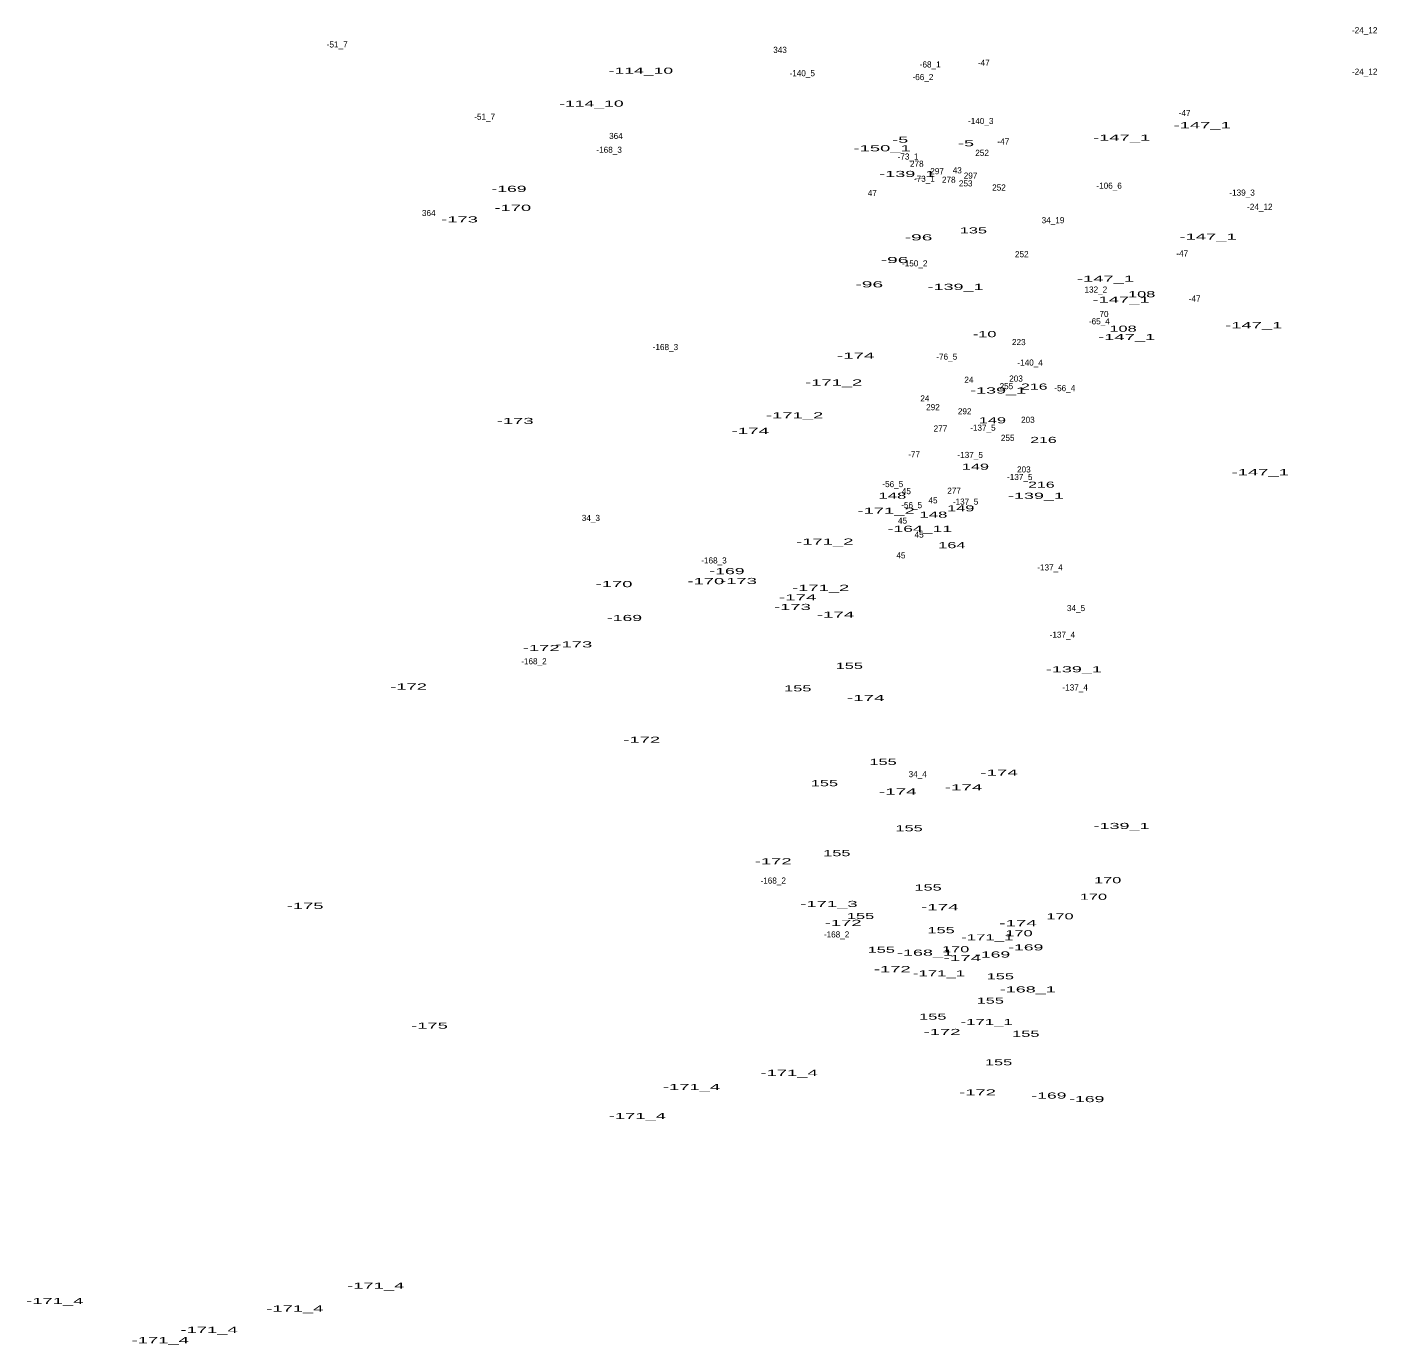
# Model space of a CAD drawing. Extents: x -662499 to -659675, y -1001682 to -998165.
# Drawn here: x -661898 to -661015, y -1001682 to -1000819 of the extents above; entities that cross this region are included whole.
import ezdxf
from ezdxf.enums import TextEntityAlignment as Align

# ---------------------------------------------------------------- set-up
doc = ezdxf.new("R2010")
doc.units = 0
doc.header["$LTSCALE"] = 1.6
doc.layers.add('24', color=7, linetype='Continuous')

msp = doc.modelspace()

# ---------------------------------------------------------------- texts
at = {"layer": '24'}
for s, p in [('-24_12', (-661022.76, -1000823.07)), ('-51_7', (-661695.372, -1000832.41)), ('343', (-661405.471, -1000835.95)), ('-140_5', (-661390.954, -1000851.22)), ('-68_1', (-661307.202, -1000845.5)), ('-47', (-661272.085, -1000844.32)), ('-24_12', (-661022.76, -1000850.22)), ('-66_2', (-661311.923, -1000853.76)), ('-47', (-661140.645, -1000877.29)), ('-51_7', (-661598.832, -1000879.73)), ('-140_3', (-661274.074, -1000882.52)), ('364', (-661512.907, -1000892.31)), ('-168_3', (-661517.342, -1000901.35)), ('252', (-661273.197, -1000903.34)), ('-47', (-661259.285, -1000895.91)), ('-73_1', (-661321.652, -1000905.77)), ('278', (-661315.953, -1000910.46)), ('-73_1', (-661310.992, -1000920.32)), ('297', (-661302.668, -1000915.34)), ('278', (-661295.013, -1000920.93)), ('43', (-661289.491, -1000914.82)), ('297', (-661280.758, -1000918.25)), ('47', (-661345.057, -1000929.67)), ('253', (-661283.937, -1000923.34)), ('252', (-661262.147, -1000926.03)), ('-106_6', (-661190.051, -1000924.83)), ('-139_3', (-661103.032, -1000929.38)), ('-24_12', (-661091.39, -1000938.66)), ('364', (-661635.427, -1000942.74)), ('34_19', (-661226.778, -1000947.42)), ('252', (-661247.217, -1000969.67)), ('-47', (-661142.195, -1000969.21)), ('-150_2', (-661317.3, -1000975.69)), ('132_2', (-661198.739, -1000992.85)), ('-47', (-661134.055, -1000998.69)), ('70', (-661193.407, -1001008.81)), ('-65_4', (-661196.452, -1001013.61)), ('223', (-661249.177, -1001027.2)), ('-168_3', (-661480.512, -1001030.45)), ('-76_5', (-661296.344, -1001036.71)), ('-140_4', (-661241.769, -1001040.61)), ('24', (-661281.841, -1001051.87)), ('203', (-661251.001, -1001051.07)), ('255', (-661257.317, -1001056.03)), ('-56_4', (-661219.052, -1001057.33)), ('24', (-661310.691, -1001064.08)), ('292', (-661305.373, -1001069.77)), ('292', (-661284.623, -1001072.48)), ('203', (-661243.241, -1001078.03)), ('277', (-661300.469, -1001083.78)), ('-137_5', (-661272.682, -1001083.22)), ('255', (-661256.447, -1001089.88)), ('-77', (-661317.735, -1001100.64)), ('-137_5', (-661281.022, -1001101.06)), ('-137_5', (-661248.552, -1001115.51)), ('203', (-661245.861, -1001110.52)), ('-56_5', (-661331.648, -1001120.13)), ('45', (-661322.771, -1001124.74)), ('277', (-661291.549, -1001124.49)), ('-56_5', (-661319.338, -1001133.9)), ('45', (-661305.351, -1001130.74)), ('-137_5', (-661284.032, -1001131.61)), ('34_3', (-661529.31, -1001142.28)), ('45', (-661325.291, -1001144.01)), ('45', (-661314.451, -1001153.21)), ('45', (-661326.361, -1001166.77)), ('-168_3', (-661448.712, -1001170.09)), ('-137_4', (-661228.776, -1001174.67)), ('34_5', (-661211.73, -1001201.26)), ('-137_4', (-661220.636, -1001218.7)), ('-168_2', (-661566.592, -1001236.08)), ('-137_4', (-661212.296, -1001253.22)), ('34_4', (-661315.374, -1001309.94)), ('-168_2', (-661409.942, -1001379.6)), ('-168_2', (-661368.462, -1001414.84))]:
    msp.add_text(s, height=4, dxfattribs=at).set_placement(p, align=Align.CENTER)
for s, width, p in [('-114_10', 2.15, (-661496.566, -1000849.59)), ('-114_10', 2.15, (-661528.946, -1000871.12)), ('-147_1', 2.25, (-661129.128, -1000885.24)), ('-5', 2.2, (-661326.774, -1000894.74)), ('-147_1', 2.25, (-661181.858, -1000893.38)), ('-150_1', 2.25, (-661338.634, -1000900.35)), ('-5', 2.2, (-661283.734, -1000897.07)), ('-139_1', 2.2, (-661322.193, -1000917.17)), ('-169', 2.15, (-661582.909, -1000926.91)), ('-170', 2.25, (-661580.431, -1000939.32)), ('-173', 2.25, (-661615.275, -1000946.92)), ('135', 2, (-661278.917, -1000954.11)), ('-96', 2.35, (-661314.813, -1000958.67)), ('-147_1', 2.25, (-661125.248, -1000958.16)), ('-96', 2.35, (-661330.523, -1000973.5)), ('-96', 2.35, (-661347.093, -1000989.41)), ('-139_1', 2.2, (-661290.593, -1000991.06)), ('-147_1', 2.25, (-661192.428, -1000985.74)), ('-147_1', 2.25, (-661182.248, -1000999.41)), ('108', 2, (-661168.744, -1000995.86)), ('108', 2, (-661180.934, -1001018.43)), ('-147_1', 2.25, (-661095.398, -1001016.14)), ('-10', 2, (-661271.557, -1001022)), ('-147_1', 2.25, (-661178.568, -1001023.94)), ('-174', 2.3, (-661355.941, -1001036.05)), ('-171_2', 2.25, (-661370.363, -1001053.62)), ('-139_1', 2.2, (-661262.753, -1001058.86)), ('216', 1.95, (-661239.063, -1001056.33)), ('-173', 2.25, (-661578.835, -1001078.8)), ('-171_2', 2.25, (-661395.953, -1001075.14)), ('149', 2, (-661266.458, -1001078.39)), ('-174', 2.3, (-661424.961, -1001085.31)), ('216', 1.95, (-661233.053, -1001091.24)), ('149', 2, (-661277.598, -1001108.74)), ('-147_1', 2.25, (-661091.128, -1001112.33)), ('216', 1.95, (-661234.413, -1001120.52)), ('148', 2.05, (-661331.933, -1001127.72)), ('-139_1', 2.2, (-661237.943, -1001127.78)), ('-171_2', 2.25, (-661336.043, -1001137.59)), ('148', 2.05, (-661305.083, -1001140.14)), ('149', 2, (-661287.198, -1001135.99)), ('-164_11', 2.15, (-661313.975, -1001149.39)), ('-171_2', 2.25, (-661376.173, -1001157.76)), ('164', 2, (-661293.008, -1001160.1)), ('-169', 2.15, (-661440.219, -1001177.09)), ('-170', 2.25, (-661514.131, -1001185.58)), ('-170', 2.25, (-661454.031, -1001183.64)), ('-173', 2.25, (-661432.655, -1001183.53)), ('-174', 2.3, (-661393.941, -1001194.31)), ('-171_2', 2.25, (-661378.893, -1001188.02)), ('-173', 2.25, (-661397.365, -1001200.53)), ('-169', 2.15, (-661507.299, -1001207.74)), ('-174', 2.3, (-661369.131, -1001205.55)), ('-172', 2.25, (-661561.845, -1001227.4)), ('-173', 2.25, (-661540.445, -1001225.03)), ('155', 2, (-661360.137, -1001239.08)), ('-139_1', 2.2, (-661213.123, -1001241.31)), ('-172', 2.25, (-661648.625, -1001252.62)), ('155', 2, (-661393.867, -1001253.82)), ('-174', 2.3, (-661349.351, -1001260.06)), ('-172', 2.25, (-661496.015, -1001287.45)), ('155', 2, (-661338.037, -1001301.92)), ('-174', 2.3, (-661262.111, -1001308.93)), ('155', 2, (-661376.417, -1001315.88)), ('-174', 2.3, (-661285.371, -1001318.63)), ('-174', 2.3, (-661328.411, -1001321.35)), ('155', 2, (-661320.977, -1001345.36)), ('-139_1', 2.2, (-661181.943, -1001343.85)), ('155', 2, (-661368.277, -1001361.65)), ('-172', 2.25, (-661409.935, -1001366.96)), ('170', 2, (-661191.009, -1001379.34)), ('155', 2, (-661308.567, -1001384.15)), ('170', 2, (-661200.319, -1001390.21)), ('-175', 2.25, (-661716.365, -1001396.16)), ('-171_3', 2.25, (-661373.463, -1001394.9)), ('-174', 2.3, (-661300.881, -1001396.98)), ('-172', 2.25, (-661364.175, -1001407.3)), ('155', 2, (-661352.767, -1001402.77)), ('-174', 2.3, (-661249.701, -1001407.46)), ('170', 2, (-661222.219, -1001403.01)), ('155', 2, (-661300.037, -1001412.08)), ('-171_1', 2.05, (-661269.829, -1001416.68)), ('170', 2, (-661249.039, -1001414.07)), ('155', 2, (-661339.197, -1001424.88)), ('170', 2, (-661290.519, -1001424.54)), ('-169', 2.15, (-661244.609, -1001423.32)), ('-168_1', 2.2, (-661310.593, -1001426.78)), ('-174', 2.3, (-661286.151, -1001430.34)), ('-169', 2.15, (-661266.319, -1001427.97)), ('-172', 2.25, (-661331.995, -1001437.56)), ('-171_1', 2.05, (-661301.429, -1001440.34)), ('155', 2, (-661261.267, -1001442.25)), ('-168_1', 2.2, (-661243.323, -1001450.83)), ('155', 2, (-661267.857, -1001458.15)), ('155', 2, (-661305.467, -1001468.63)), ('-175', 2.25, (-661634.935, -1001474.51)), ('-172', 2.25, (-661299.425, -1001478.67)), ('-171_1', 2.05, (-661270.209, -1001472.15)), ('155', 2, (-661244.597, -1001479.87)), ('155', 2, (-661262.427, -1001498.49)), ('-171_4', 2.25, (-661399.538, -1001505.42)), ('-171_4', 2.25, (-661463.398, -1001514.68)), ('-172', 2.25, (-661276.165, -1001518.24)), ('-169', 2.15, (-661229.479, -1001520.29)), ('-169', 2.15, (-661204.669, -1001522.61)), ('-171_4', 2.25, (-661498.878, -1001533.68)), ('-171_4', 2.25, (-661670.158, -1001644.73)), ('-171_4', 2.25, (-661880.218, -1001654.78)), ('-171_4', 2.25, (-661723.088, -1001659.66)), ('-171_4', 2.25, (-661811.198, -1001680.38)), ('-171_4', 2.25, (-661779.218, -1001673.59))]:
    msp.add_text(s, height=4, dxfattribs=dict(at, width=width)).set_placement(p, align=Align.CENTER)

doc.saveas('drawing.dxf')
